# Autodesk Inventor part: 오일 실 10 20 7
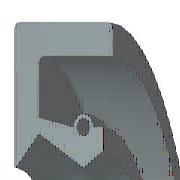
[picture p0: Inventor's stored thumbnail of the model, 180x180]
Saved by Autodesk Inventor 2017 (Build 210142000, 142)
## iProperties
IsCustomPart: 1
Created: 2012-02
Part Number: 오일 실 10 20 7
Material: 고무
Description: 오일-실
Document SubType Name: Modeling
Standard: KS B 2804
Designer: mduedu
Standards Organization: KS
Language: ko-KR
Size Designation: D - 10 20 7
Categories: <MemberInstance><Categories><Category DisplayName="샤프트 부품" InternalName="7f7aeb1f-a693-4053-b835-cee3144e0d98" Mnemonic="SHFT"><Category DisplayName="실링" Intern
Density: 0.93 g/cm^3
Mass: 1.11329 g
Surface Area: 16.3871 cm^2
Volume: 1.19708 cm^3
Appearance: 분홍색
Author: mduedu
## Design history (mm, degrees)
revolve "본체" stored, may be unused: angle "d17" = 90 deg
revolve "스프링1" stored, may be unused: angle "d18" = 90 deg
body "Solid1"
sketch "스케치1"
  geometry: L1 (0, 10)-(7, 10); L2 (7, 8.25)-(1.75, 8.25); L3 (1.75, 6.75)-(4.9, 5); L4 (4.9, 5)-(0, 5); L5 (0, 0)-(9.586, 0) reference; L6 (4.9, 5)-(6.3, 5.875); L7 (0, 18)-(0, -3) reference; L8 (-1.941, 0)-(11.507, 0) reference; L9 (4.2, 7.1)-(1.75, 7.59); L10 (1.75, 7.59)-(1.75, 8.25); L11 (0, 10)-(0, 5.088); L12 (4.9, 5)-(0, 5); L13 (1.75, 6.75)-(0.152, 5.028); L14 (7, 10)-(7, 8.25); L15 (5.6, 7.1)-(6.3, 7.1); L16 (6.3, 7.1)-(6.3, 5.875); C1 r 0.455 at (4.9, 7.1); A1 r 0.7 centre (4.9, 7.1) between (5.6, 7.1) and (4.2, 7.1); A2 r 0.088 centre (0.088, 5.088) between (0, 5.088) and (0.152, 5.028); 1 further point
  constraints: 28 end point, 5 horizontal alignment, 5 point on line, 4 point on circle, 4 vertical alignment, 3 centre point, 3 tangent, 2 collinear, 2 horizontal, 2 perpendicular, 1 coincident, 1 parallel
  dimensions: "d0" = 20 diameter of L1 L5 (= SD2); "d1" = 1.75 distance of L1.end L2.start (= SD); "d2" = 0.91 diameter of C1 (= SPDI); "d3" = 1.4 diameter of A1 (= SPDA); "d4" = 10 diameter of L3.end L5 (= NND); "d5" = 13.5 diameter of L3.start L5 (= TKDM); "d7" = 15.18 diameter of L9.end L5 (= TKDM + 0.24 x SWDT); "d8" = 1.75 distance between parallel lines of L11 L10 (= SD); "d9" = 4.9 distance from line of L11 C1.centre (= SPDST); "d10" = 14.2 diameter of C1.centre L5 (= HLDM); "d11" = 0.0875 radius of A2 (= 0.25 x LAB); "d12" = 6.3 distance between parallel lines of L11 L16 (= SDI); "d13" = 11.75 diameter of L6.end L5 (= ABDM); "d14" = 7 distance from line of L11 L1.end (= SWDT)
fillet "모깎기1" dims "d6" = 0.3 (= RR)
other parameters: "SD2" = 20 [user parameter; used in 1 equation term], "SWDT" = 7 [user parameter; used in 2 equation terms], "RR" = 0.3 [user parameter; used in 1 equation term], "SD" = 1.75 [user parameter; used in 2 equation terms], "NND" = 10 [user parameter; used in 1 equation term], "SPDA" = 1.4 [user parameter; used in 1 equation term], "SPDI" = 0.91 [user parameter; used in 1 equation term], "TKDM" = 13.5 [user parameter; used in 2 equation terms], "HLDM" = 14.2 [user parameter; used in 1 equation term], "ABDM" = 11.75 [user parameter; used in 1 equation term], "SDI" = 6.3 [user parameter; used in 1 equation term], "SPDST" = 4.9 [user parameter; used in 1 equation term], "LAB" = 0.35 [user parameter; used in 1 equation term], "d15" = 0, "d16" = 0, "d19" = 0
